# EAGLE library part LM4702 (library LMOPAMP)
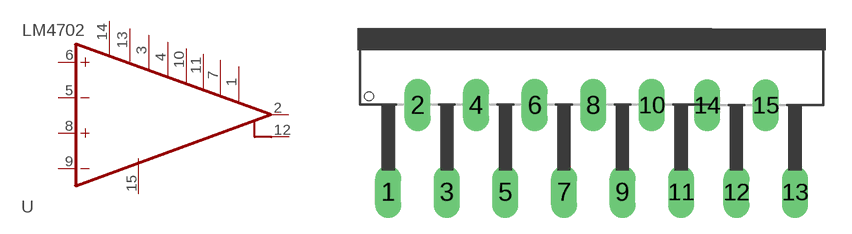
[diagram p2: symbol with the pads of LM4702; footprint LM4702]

Designator prefix -

## LM4702  [LM4702]
1  V+7  pwr
2  OUT  out
3  V+2  pwr
4  V+3  pwr
5  -INA  in
6  +INA  in
7  V+6  pwr
8  +INB  in
9  -INB  in
10  V+4  pwr
11  V+5  pwr
12  OUT1  out
13  V+  pwr
14  V+1  pwr
15  V-  pwr

## Footprint LM4702 (pad centres in mm)
drill 1.016 long: 1 0.381,1.905; 2 2.083,6.96; 3 3.785,1.905; 4 5.486,6.96; 5 7.188,1.905; 6 8.89,6.96; 7 10.592,1.905; 8 12.294,6.96; 9 13.995,1.905; 10 15.697,6.96; 11 17.399,1.905; 12 20.615,1.895; 13 24.019,1.895; 14 18.914,6.95; 15 22.317,6.95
